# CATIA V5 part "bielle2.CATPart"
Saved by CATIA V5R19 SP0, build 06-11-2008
Part number: Pièce2
Bounding box of the stored display mesh (mm): x -20 to 0, y -12.31 to 393.376, z -12.5 to 12.5
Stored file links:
  G:\EU_thinkMotion\CFAO_2010\SIL_groupe1\SIL_groupe1\A reprendre\lalpha\lalpha\Alpha.mécanisme\bielle2.CATPart
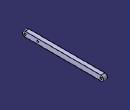
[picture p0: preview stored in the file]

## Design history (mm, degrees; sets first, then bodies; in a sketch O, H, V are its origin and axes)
Body1 (main body)
  Line1: stored without definition
  Line2: stored without definition
  Sketch1 on Line1, origin (0, 0, 0), H (0, 1, 0), V (0, 0, 1)
    point P1 (0, -12.5)
    line L1 (0, -12.5) -> (381.0657, -12.5)
    line L2 (381.0657, 12.5) -> (0, 12.5)
    arc A1 centre (0, 0) radius 12.5 from (0, 12.5) to (0, -12.5) ccw
    arc A2 centre (381.0657, 0) radius 12.5 from (381.0657, -12.5) to (381.0657, 12.5) ccw
    circle A3 centre (63.6233, 0) radius 5
    point P7 (63.6233, 0)
    circle A4 centre (381.0657, 0) radius 5
    circle A5 centre (0, 0) radius 5
    coincidence: P1 V, P7 H
    horizontal: L1 H, L2 H
    tangency: A1 L1, A2 L2
  Pad1: profile Sketch1, direction (-1, 0, 0), length 20
  Line3: stored without definition
  Line4: stored without definition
